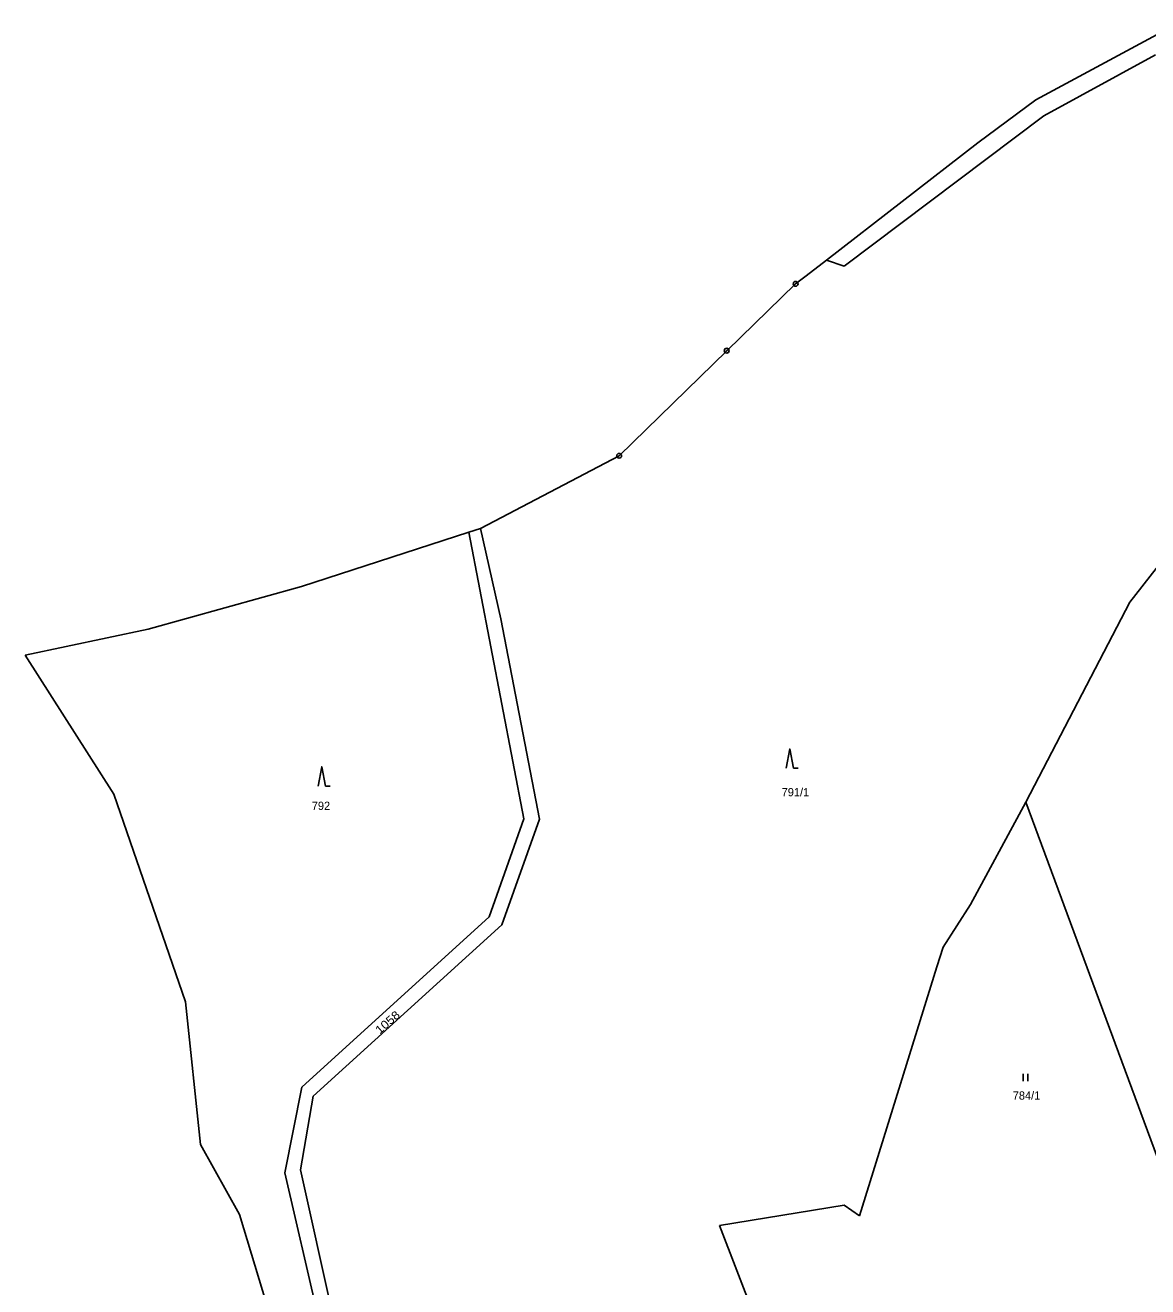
# Model space of a CAD drawing. Extents: x -744132 to -742433, y -984679 to -982287.
# Drawn here: x -744132.4 to -743900.1, y -983014.5 to -982753.5 of the extents above; entities that cross this region are included whole.
import ezdxf

# ---------------------------------------------------------------- set-up
doc = ezdxf.new("R2010")
doc.units = 0
doc.header["$LTSCALE"] = 0.68
for name, color, linetype, lineweight in [('1', 7, 'Continuous', 25), ('3', 7, 'Continuous', 25), ('8', 7, 'Continuous', 25)]:
    doc.layers.add(name, color=color, linetype=linetype, lineweight=lineweight)
doc.layers.add('2', color=7, linetype='Continuous')

msp = doc.modelspace()

# ---------------------------------------------------------------- linework, layer by layer
at = {"layer": '1'}
for p, q in [((-743894.57, -982753.52), (-743923.29, -982768.96)), ((-743921.67, -982772.27), (-743898.51, -982759.63)), ((-743923.29, -982768.96), (-743935.27, -982777.86)), ((-743962.98, -982803.37), (-743921.67, -982772.27)), ((-743935.27, -982777.86), (-743966.58, -982802.09)), ((-743966.58, -982802.09), (-743970.84, -982805.36)), ((-743966.58, -982802.09), (-743962.98, -982803.37)), ((-743973.01, -982807.02), (-743987.27, -982820.85)), ((-743970.84, -982805.36), (-743973.01, -982807.02)), ((-743987.27, -982820.85), (-744009.52, -982842.59)), ((-744038.23, -982857.65), (-744009.52, -982842.59)), ((-743903.83, -982872.89), (-743886.85, -982851.02)), ((-744040.62, -982858.42), (-744075.25, -982869.61)), ((-744038.23, -982857.65), (-744040.62, -982858.42)), ((-744075.25, -982869.61), (-744107.02, -982878.46)), ((-743925.38, -982914.22), (-743903.83, -982872.89)), ((-744132.43, -982883.87), (-744107.02, -982878.46)), ((-744132.43, -982883.87), (-744114.06, -982912.62)), ((-744114.06, -982912.62), (-744099.26, -982955.57)), ((-743925.38, -982914.22), (-743936.8, -982935.4)), ((-743925.38, -982914.22), (-743892.48, -983003.17)), ((-744033.81, -982939.66), (-744026.03, -982917.8)), ((-743942.46, -982944.27), (-743936.8, -982935.4)), ((-744075.22, -982973.24), (-744036.44, -982937.99)), ((-744072.82, -982975.06), (-744033.81, -982939.66)), ((-743942.46, -982944.27), (-743943.79, -982948.31)), ((-743943.79, -982948.31), (-743959.8, -982999.81)), ((-744099.26, -982955.57), (-744096.14, -982985.07)), ((-744078.73, -982990.95), (-744075.22, -982973.24)), ((-744075.46, -982990.35), (-744072.82, -982975.06)), ((-744096.14, -982985.07), (-744088.07, -982999.56)), ((-744071.39, -983022.53), (-744078.73, -982990.95)), ((-744068.32, -983022.46), (-744075.46, -982990.35)), ((-743988.75, -983001.83), (-743962.95, -982997.64)), ((-743959.8, -982999.81), (-743962.95, -982997.64)), ((-744088.07, -982999.56), (-744082.42, -983018.25)), ((-743988.75, -983001.83), (-743978.43, -983028.72))]:
    msp.add_line(p, q, dxfattribs=at)
for points in [[(-744036.44, -982937.99), (-744029.26, -982917.67), (-744040.62, -982858.42)], [(-744026.03, -982917.8), (-744034.02, -982876.36), (-744038.23, -982857.65)]]:
    msp.add_lwpolyline(points, dxfattribs=at)
at = {"layer": '3'}
for p, q in [((-743973.47, -982907.23), (-743972.474, -982907.23)), ((-744070.3, -982910.92), (-744069.304, -982910.92)), ((-743925.921, -982971.95), (-743925.921, -982970.45)), ((-743924.92, -982971.95), (-743924.92, -982970.45))]:
    msp.add_line(p, q, dxfattribs=at)
for points in [[(-743973.47, -982907.23), (-743974.22, -982903.23), (-743974.97, -982907.23)], [(-744070.3, -982910.92), (-744071.05, -982906.92), (-744071.8, -982910.92)]]:
    msp.add_lwpolyline(points, dxfattribs=at)
at = {"layer": '8'}
for centre, radius in [((-743973.01, -982807.0199), 0.5), ((-743973.01, -982807.0199), 0.0303), ((-743987.27, -982820.8499), 0.5), ((-743987.27, -982820.8499), 0.0303), ((-744009.52, -982842.5899), 0.5), ((-744009.52, -982842.5899), 0.0303)]:
    msp.add_circle(centre, radius, dxfattribs=at)

# ---------------------------------------------------------------- texts
at = {"layer": '2'}
for s, p in [('791/1', (-743975.89, -982913.035)), ('792', (-744073.12, -982915.855)), ('784/1', (-743928.07, -982975.795))]:
    msp.add_text(s, height=1.7, dxfattribs=at).set_placement(p)
at = {"layer": '2', "width": 1.15}
msp.add_text('1058', height=1.7, rotation=41, dxfattribs=at).set_placement((-744059.091, -982962.35))

doc.saveas('drawing.dxf')
